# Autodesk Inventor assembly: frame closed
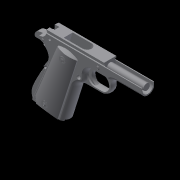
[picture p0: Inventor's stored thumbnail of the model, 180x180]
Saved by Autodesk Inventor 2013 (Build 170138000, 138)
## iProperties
Created: 2013-01
Part Number: frame closed
Document SubType Name: Assembly
Designer: John
Author: John
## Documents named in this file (6)
- C:\Users\George\Desktop\1911\1911 pegs\frame closed.iam
- C:\Users\George\Desktop\1911\1911 frame closed.ipt
- C:\Users\George\Desktop\1911\1911 back grip.ipt
- C:\Users\George\Desktop\1911\1911 pegs\grip peg.ipt
- C:\Users\George\Desktop\1911\1911 pegs\.201 dia.ipt
- C:\Users\George\Desktop\1911\1911 pegs\.158 dia x2.ipt
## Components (9 placed, 5 different names)
1. 1911 frame closed:1 — Mate:1, Mate:2, Insert:1, Insert:2, Insert:3, Insert:4, Mate:3, Mate:4, Mate:5, Mate:6, Mate:7, Mate:8
2. 1911 back grip:1 — Mate:1, Mate:2
3. grip peg:1 — Insert:1
4. grip peg:2 — Insert:2
5. grip peg:3 — Insert:3
6. grip peg:4 — Insert:4
7. .201 dia:1 — Mate:3, Mate:4
8. .158 dia x2:1 — Mate:5, Mate:6
9. .158 dia x2:2 — Mate:7, Mate:8
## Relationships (12: Mate 8, Insert 4)
- Mate:1: 1911 frame closed:1 ↔ 1911 back grip:1
- Mate:2: 1911 frame closed:1 ↔ 1911 back grip:1
- Insert:1: 1911 frame closed:1 ↔ grip peg:1
- Insert:2: 1911 frame closed:1 ↔ grip peg:2
- Insert:3: 1911 frame closed:1 ↔ grip peg:3
- Insert:4: 1911 frame closed:1 ↔ grip peg:4
- Mate:3: 1911 frame closed:1 ↔ .201 dia:1
- Mate:4: 1911 frame closed:1 ↔ .201 dia:1
- Mate:5: 1911 frame closed:1 ↔ .158 dia x2:1
- Mate:6: 1911 frame closed:1 ↔ .158 dia x2:1
- Mate:7: 1911 frame closed:1 ↔ .158 dia x2:2
- Mate:8: 1911 frame closed:1 ↔ .158 dia x2:2
